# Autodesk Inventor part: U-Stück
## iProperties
Created: 2007-11
Part Number: U-Stück
Document SubType Name: Modeling
Designer: Benno
Manufacturer: Standard
Standards Organization: Custom
Author: Benno
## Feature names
1. Extrusion1
2. Extrusion2
3. Bohrung1 [Hole]
4. Extrusion3
5. Fase1 [Chamfer]
6. Extrusion4
7. Extrusion5
